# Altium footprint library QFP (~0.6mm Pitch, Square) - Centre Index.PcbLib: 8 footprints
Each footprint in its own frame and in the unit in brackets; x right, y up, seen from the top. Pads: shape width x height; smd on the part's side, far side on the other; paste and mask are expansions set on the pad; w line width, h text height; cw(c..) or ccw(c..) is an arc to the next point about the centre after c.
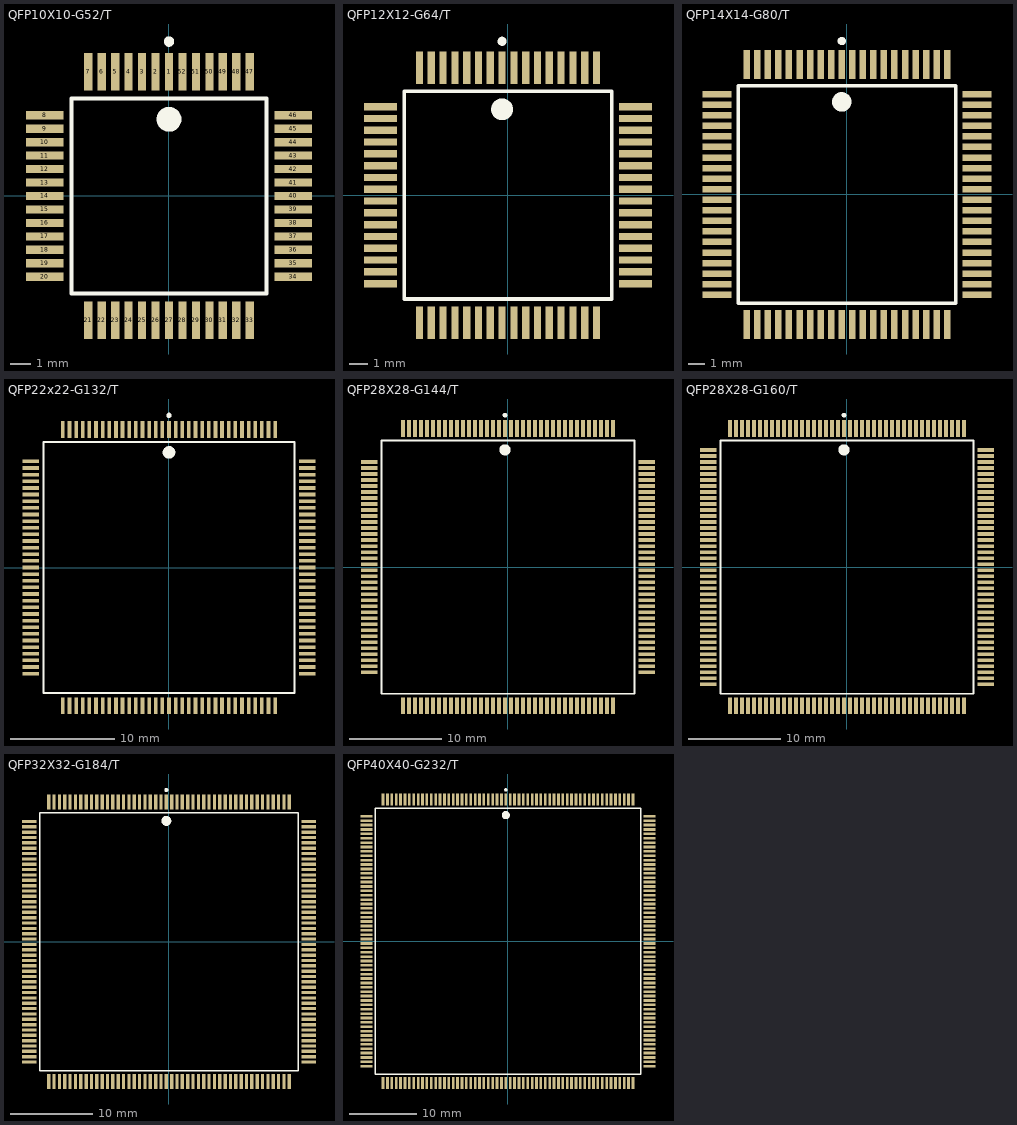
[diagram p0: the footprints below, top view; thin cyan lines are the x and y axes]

## QFP10X10-G52/T [mm]
pads (52):
  rect 0.4x1.8 smd: 1(0,6) 2(-0.65,6) 3(-1.3,6) 4(-1.95,6) 5(-2.6,6) 6(-3.25,6) 7(-3.9,6) 21(-3.9,-6) 22(-3.25,-6) 23(-2.6,-6) 24(-1.95,-6) 25(-1.3,-6) 26(-0.65,-6) 27(0,-6) 28(0.65,-6) 29(1.3,-6) 30(1.95,-6) 31(2.6,-6) 32(3.25,-6) 33(3.9,-6) 47(3.9,6) 48(3.25,6) 49(2.6,6) 50(1.95,6) 51(1.3,6) 52(0.65,6)
  rect 1.8x0.4 smd: 8(-6,3.9) 9(-6,3.25) 10(-6,2.6) 11(-6,1.95) 12(-6,1.3) 13(-6,0.65) 14(-6,0) 15(-6,-0.65) 16(-6,-1.3) 17(-6,-1.95) 18(-6,-2.6) 19(-6,-3.25) 20(-6,-3.9) 34(6,-3.9) 35(6,-3.25) 36(6,-2.6) 37(6,-1.95) 38(6,-1.3) 39(6,-0.65) 40(6,0) 41(6,0.65) 42(6,1.3) 43(6,1.95) 44(6,2.6) 45(6,3.25) 46(6,3.9)
Top Overlay:
  circle w0.6: c0,3.7 r0.3
  circle w0.25: c0,7.45 r0.125
  lines w0.2: -4.7,-4.7 -4.7,4.7 4.7,4.7 4.7,-4.7 -4.7,-4.7

## QFP12X12-G64/T [mm]
pads (64):
  rect 0.4x1.8 smd: 1(-0.325,7.025) 2(-0.975,7.025) 3(-1.625,7.025) 4(-2.275,7.025) 5(-2.925,7.025) 6(-3.575,7.025) 7(-4.225,7.025) 8(-4.875,7.025) 25(-4.875,-7.025) 26(-4.225,-7.025) 27(-3.575,-7.025) 28(-2.925,-7.025) 29(-2.275,-7.025) 30(-1.625,-7.025) 31(-0.975,-7.025) 32(-0.325,-7.025) 33(0.325,-7.025) 34(0.975,-7.025) 35(1.625,-7.025) 36(2.275,-7.025) 37(2.925,-7.025) 38(3.575,-7.025) 39(4.225,-7.025) 40(4.875,-7.025) 57(4.875,7.025) 58(4.225,7.025) 59(3.575,7.025) 60(2.925,7.025) 61(2.275,7.025) 62(1.625,7.025) 63(0.975,7.025) 64(0.325,7.025)
  rect 1.8x0.4 smd: 9(-7.025,4.875) 10(-7.025,4.225) 11(-7.025,3.575) 12(-7.025,2.925) 13(-7.025,2.275) 14(-7.025,1.625) 15(-7.025,0.975) 16(-7.025,0.325) 17(-7.025,-0.325) 18(-7.025,-0.975) 19(-7.025,-1.625) 20(-7.025,-2.275) 21(-7.025,-2.925) 22(-7.025,-3.575) 23(-7.025,-4.225) 24(-7.025,-4.875) 41(7.025,-4.875) 42(7.025,-4.225) 43(7.025,-3.575) 44(7.025,-2.925) 45(7.025,-2.275) 46(7.025,-1.625) 47(7.025,-0.975) 48(7.025,-0.325) 49(7.025,0.325) 50(7.025,0.975) 51(7.025,1.625) 52(7.025,2.275) 53(7.025,2.925) 54(7.025,3.575) 55(7.025,4.225) 56(7.025,4.875)
Top Overlay:
  circle w0.25: c-0.325,8.475 r0.125
  circle w0.6: c-0.325,4.725 r0.3
  lines w0.2: -5.725,-5.725 5.725,-5.725 5.725,5.725 -5.725,5.725 -5.725,-5.725

## QFP14X14-G80/T [mm]
pads (80):
  rect 0.4x1.8 smd: 1(-0.325,8) 2(-0.975,8) 3(-1.625,8) 4(-2.275,8) 5(-2.925,8) 6(-3.575,8) 7(-4.225,8) 8(-4.875,8) 9(-5.525,8) 10(-6.175,8) 31(-6.175,-8) 32(-5.525,-8) 33(-4.875,-8) 34(-4.225,-8) 35(-3.575,-8) 36(-2.925,-8) 37(-2.275,-8) 38(-1.625,-8) 39(-0.975,-8) 40(-0.325,-8) 41(0.325,-8) 42(0.975,-8) 43(1.625,-8) 44(2.275,-8) 45(2.925,-8) 46(3.575,-8) 47(4.225,-8) 48(4.875,-8) 49(5.525,-8) 50(6.175,-8) 71(6.175,8) 72(5.525,8) 73(4.875,8) 74(4.225,8) 75(3.575,8) 76(2.925,8) 77(2.275,8) 78(1.625,8) 79(0.975,8) 80(0.325,8)
  rect 1.8x0.4 smd: 11(-8,6.175) 12(-8,5.525) 13(-8,4.875) 14(-8,4.225) 15(-8,3.575) 16(-8,2.925) 17(-8,2.275) 18(-8,1.625) 19(-8,0.975) 20(-8,0.325) 21(-8,-0.325) 22(-8,-0.975) 23(-8,-1.625) 24(-8,-2.275) 25(-8,-2.925) 26(-8,-3.575) 27(-8,-4.225) 28(-8,-4.875) 29(-8,-5.525) 30(-8,-6.175) 51(8,-6.175) 52(8,-5.525) 53(8,-4.875) 54(8,-4.225) 55(8,-3.575) 56(8,-2.925) 57(8,-2.275) 58(8,-1.625) 59(8,-0.975) 60(8,-0.325) 61(8,0.325) 62(8,0.975) 63(8,1.625) 64(8,2.275) 65(8,2.925) 66(8,3.575) 67(8,4.225) 68(8,4.875) 69(8,5.525) 70(8,6.175)
Top Overlay:
  circle w0.25: c-0.325,9.45 r0.125
  circle w0.6: c-0.325,5.7 r0.3
  lines w0.2: -6.7,-6.7 6.7,-6.7 6.7,6.7 -6.7,6.7 -6.7,-6.7

## QFP22x22-G132/T [mm]
pads (132):
  rect 0.35x1.6 smd: 1(0,13.225) 2(-0.635,13.225) 3(-1.27,13.225) 4(-1.905,13.225) 5(-2.54,13.225) 6(-3.175,13.225) 7(-3.81,13.225) 8(-4.445,13.225) 9(-5.08,13.225) 10(-5.715,13.225) 11(-6.35,13.225) 12(-6.985,13.225) 13(-7.62,13.225) 14(-8.255,13.225) 15(-8.89,13.225) 16(-9.525,13.225) 17(-10.16,13.225) 51(-10.16,-13.225) 52(-9.525,-13.225) 53(-8.89,-13.225) 54(-8.255,-13.225) 55(-7.62,-13.225) 56(-6.985,-13.225) 57(-6.35,-13.225) 58(-5.715,-13.225) 59(-5.08,-13.225) 60(-4.445,-13.225) 61(-3.81,-13.225) 62(-3.175,-13.225) 63(-2.54,-13.225) 64(-1.905,-13.225) 65(-1.27,-13.225) 66(-0.635,-13.225) 67(0,-13.225) 68(0.635,-13.225) 69(1.27,-13.225) 70(1.905,-13.225) 71(2.54,-13.225) 72(3.175,-13.225) 73(3.81,-13.225) 74(4.445,-13.225) 75(5.08,-13.225) 76(5.715,-13.225) 77(6.35,-13.225) 78(6.985,-13.225) 79(7.62,-13.225) 80(8.255,-13.225) 81(8.89,-13.225) 82(9.525,-13.225) 83(10.16,-13.225) 117(10.16,13.225) 118(9.525,13.225) 119(8.89,13.225) 120(8.255,13.225) 121(7.62,13.225) 122(6.985,13.225) 123(6.35,13.225) 124(5.715,13.225) 125(5.08,13.225) 126(4.445,13.225) 127(3.81,13.225) 128(3.175,13.225) 129(2.54,13.225) 130(1.905,13.225) 131(1.27,13.225) 132(0.635,13.225)
  rect 1.6x0.35 smd: 18(-13.225,10.16) 19(-13.225,9.525) 20(-13.225,8.89) 21(-13.225,8.255) 22(-13.225,7.62) 23(-13.225,6.985) 24(-13.225,6.35) 25(-13.225,5.715) 26(-13.225,5.08) 27(-13.225,4.445) 28(-13.225,3.81) 29(-13.225,3.175) 30(-13.225,2.54) 31(-13.225,1.905) 32(-13.225,1.27) 33(-13.225,0.635) 34(-13.225,0) 35(-13.225,-0.635) 36(-13.225,-1.27) 37(-13.225,-1.905) 38(-13.225,-2.54) 39(-13.225,-3.175) 40(-13.225,-3.81) 41(-13.225,-4.445) 42(-13.225,-5.08) 43(-13.225,-5.715) 44(-13.225,-6.35) 45(-13.225,-6.985) 46(-13.225,-7.62) 47(-13.225,-8.255) 48(-13.225,-8.89) 49(-13.225,-9.525) 50(-13.225,-10.16) 84(13.225,-10.16) 85(13.225,-9.525) 86(13.225,-8.89) 87(13.225,-8.255) 88(13.225,-7.62) 89(13.225,-6.985) 90(13.225,-6.35) 91(13.225,-5.715) 92(13.225,-5.08) 93(13.225,-4.445) 94(13.225,-3.81) 95(13.225,-3.175) 96(13.225,-2.54) 97(13.225,-1.905) 98(13.225,-1.27) 99(13.225,-0.635) 100(13.225,0) 101(13.225,0.635) 102(13.225,1.27) 103(13.225,1.905) 104(13.225,2.54) 105(13.225,3.175) 106(13.225,3.81) 107(13.225,4.445) 108(13.225,5.08) 109(13.225,5.715) 110(13.225,6.35) 111(13.225,6.985) 112(13.225,7.62) 113(13.225,8.255) 114(13.225,8.89) 115(13.225,9.525) 116(13.225,10.16)
Top Overlay:
  circle w0.25: c0,14.575 r0.125
  circle w0.6: c0,11.025 r0.3
  lines w0.2: -12.025,-12.025 12.025,-12.025 12.025,12.025 -12.025,12.025 -12.025,-12.025

## QFP28X28-G144/T [mm]
pads (144):
  rect 0.4x1.8 smd: 1(-0.325,15) 2(-0.975,15) 3(-1.625,15) 4(-2.275,15) 5(-2.925,15) 6(-3.575,15) 7(-4.225,15) 8(-4.875,15) 9(-5.525,15) 10(-6.175,15) 11(-6.825,15) 12(-7.475,15) 13(-8.125,15) 14(-8.775,15) 15(-9.425,15) 16(-10.075,15) 17(-10.725,15) 18(-11.375,15) 55(-11.375,-15) 56(-10.725,-15) 57(-10.075,-15) 58(-9.425,-15) 59(-8.775,-15) 60(-8.125,-15) 61(-7.475,-15) 62(-6.825,-15) 63(-6.175,-15) 64(-5.525,-15) 65(-4.875,-15) 66(-4.225,-15) 67(-3.575,-15) 68(-2.925,-15) 69(-2.275,-15) 70(-1.625,-15) 71(-0.975,-15) 72(-0.325,-15) 73(0.325,-15) 74(0.975,-15) 75(1.625,-15) 76(2.275,-15) 77(2.925,-15) 78(3.575,-15) 79(4.225,-15) 80(4.875,-15) 81(5.525,-15) 82(6.175,-15) 83(6.825,-15) 84(7.475,-15) 85(8.125,-15) 86(8.775,-15) 87(9.425,-15) 88(10.075,-15) 89(10.725,-15) 90(11.375,-15) 127(11.375,15) 128(10.725,15) 129(10.075,15) 130(9.425,15) 131(8.775,15) 132(8.125,15) 133(7.475,15) 134(6.825,15) 135(6.175,15) 136(5.525,15) 137(4.875,15) 138(4.225,15) 139(3.575,15) 140(2.925,15) 141(2.275,15) 142(1.625,15) 143(0.975,15) 144(0.325,15)
  rect 1.8x0.4 smd: 19(-15,11.375) 20(-15,10.725) 21(-15,10.075) 22(-15,9.425) 23(-15,8.775) 24(-15,8.125) 25(-15,7.475) 26(-15,6.825) 27(-15,6.175) 28(-15,5.525) 29(-15,4.875) 30(-15,4.225) 31(-15,3.575) 32(-15,2.925) 33(-15,2.275) 34(-15,1.625) 35(-15,0.975) 36(-15,0.325) 37(-15,-0.325) 38(-15,-0.975) 39(-15,-1.625) 40(-15,-2.275) 41(-15,-2.925) 42(-15,-3.575) 43(-15,-4.225) 44(-15,-4.875) 45(-15,-5.525) 46(-15,-6.175) 47(-15,-6.825) 48(-15,-7.475) 49(-15,-8.125) 50(-15,-8.775) 51(-15,-9.425) 52(-15,-10.075) 53(-15,-10.725) 54(-15,-11.375) 91(15,-11.375) 92(15,-10.725) 93(15,-10.075) 94(15,-9.425) 95(15,-8.775) 96(15,-8.125) 97(15,-7.475) 98(15,-6.825) 99(15,-6.175) 100(15,-5.525) 101(15,-4.875) 102(15,-4.225) 103(15,-3.575) 104(15,-2.925) 105(15,-2.275) 106(15,-1.625) 107(15,-0.975) 108(15,-0.325) 109(15,0.325) 110(15,0.975) 111(15,1.625) 112(15,2.275) 113(15,2.925) 114(15,3.575) 115(15,4.225) 116(15,4.875) 117(15,5.525) 118(15,6.175) 119(15,6.825) 120(15,7.475) 121(15,8.125) 122(15,8.775) 123(15,9.425) 124(15,10.075) 125(15,10.725) 126(15,11.375)
Top Overlay:
  circle w0.6: c-0.325,12.7 r0.3
  circle w0.25: c-0.325,16.45 r0.125
  lines w0.2: -13.7,-13.7 -13.7,13.7 13.7,13.7 13.7,-13.7 -13.7,-13.7

## QFP28X28-G160/T [mm]
pads (160):
  rect 0.4x1.8 smd: 1(-0.325,15) 2(-0.975,15) 3(-1.625,15) 4(-2.275,15) 5(-2.925,15) 6(-3.575,15) 7(-4.225,15) 8(-4.875,15) 9(-5.525,15) 10(-6.175,15) 11(-6.825,15) 12(-7.475,15) 13(-8.125,15) 14(-8.775,15) 15(-9.425,15) 16(-10.075,15) 17(-10.725,15) 18(-11.375,15) 19(-12.025,15) 20(-12.675,15) 61(-12.675,-15) 62(-12.025,-15) 63(-11.375,-15) 64(-10.725,-15) 65(-10.075,-15) 66(-9.425,-15) 67(-8.775,-15) 68(-8.125,-15) 69(-7.475,-15) 70(-6.825,-15) 71(-6.175,-15) 72(-5.525,-15) 73(-4.875,-15) 74(-4.225,-15) 75(-3.575,-15) 76(-2.925,-15) 77(-2.275,-15) 78(-1.625,-15) 79(-0.975,-15) 80(-0.325,-15) 81(0.325,-15) 82(0.975,-15) 83(1.625,-15) 84(2.275,-15) 85(2.925,-15) 86(3.575,-15) 87(4.225,-15) 88(4.875,-15) 89(5.525,-15) 90(6.175,-15) 91(6.825,-15) 92(7.475,-15) 93(8.125,-15) 94(8.775,-15) 95(9.425,-15) 96(10.075,-15) 97(10.725,-15) 98(11.375,-15) 99(12.025,-15) 100(12.675,-15) 141(12.675,15) 142(12.025,15) 143(11.375,15) 144(10.725,15) 145(10.075,15) 146(9.425,15) 147(8.775,15) 148(8.125,15) 149(7.475,15) 150(6.825,15) 151(6.175,15) 152(5.525,15) 153(4.875,15) 154(4.225,15) 155(3.575,15) 156(2.925,15) 157(2.275,15) 158(1.625,15) 159(0.975,15) 160(0.325,15)
  rect 1.8x0.4 smd: 21(-15,12.675) 22(-15,12.025) 23(-15,11.375) 24(-15,10.725) 25(-15,10.075) 26(-15,9.425) 27(-15,8.775) 28(-15,8.125) 29(-15,7.475) 30(-15,6.825) 31(-15,6.175) 32(-15,5.525) 33(-15,4.875) 34(-15,4.225) 35(-15,3.575) 36(-15,2.925) 37(-15,2.275) 38(-15,1.625) 39(-15,0.975) 40(-15,0.325) 41(-15,-0.325) 42(-15,-0.975) 43(-15,-1.625) 44(-15,-2.275) 45(-15,-2.925) 46(-15,-3.575) 47(-15,-4.225) 48(-15,-4.875) 49(-15,-5.525) 50(-15,-6.175) 51(-15,-6.825) 52(-15,-7.475) 53(-15,-8.125) 54(-15,-8.775) 55(-15,-9.425) 56(-15,-10.075) 57(-15,-10.725) 58(-15,-11.375) 59(-15,-12.025) 60(-15,-12.675) 101(15,-12.675) 102(15,-12.025) 103(15,-11.375) 104(15,-10.725) 105(15,-10.075) 106(15,-9.425) 107(15,-8.775) 108(15,-8.125) 109(15,-7.475) 110(15,-6.825) 111(15,-6.175) 112(15,-5.525) 113(15,-4.875) 114(15,-4.225) 115(15,-3.575) 116(15,-2.925) 117(15,-2.275) 118(15,-1.625) 119(15,-0.975) 120(15,-0.325) 121(15,0.325) 122(15,0.975) 123(15,1.625) 124(15,2.275) 125(15,2.925) 126(15,3.575) 127(15,4.225) 128(15,4.875) 129(15,5.525) 130(15,6.175) 131(15,6.825) 132(15,7.475) 133(15,8.125) 134(15,8.775) 135(15,9.425) 136(15,10.075) 137(15,10.725) 138(15,11.375) 139(15,12.025) 140(15,12.675)
Top Overlay:
  circle w0.25: c-0.325,16.45 r0.125
  circle w0.6: c-0.325,12.7 r0.3
  lines w0.2: -13.7,-13.7 13.7,-13.7 13.7,13.7 -13.7,13.7 -13.7,-13.7

## QFP32X32-G184/T [mm]
pads (184):
  rect 0.4x1.8 smd: 1(-0.325,17) 2(-0.975,17) 3(-1.625,17) 4(-2.275,17) 5(-2.925,17) 6(-3.575,17) 7(-4.225,17) 8(-4.875,17) 9(-5.525,17) 10(-6.175,17) 11(-6.825,17) 12(-7.475,17) 13(-8.125,17) 14(-8.775,17) 15(-9.425,17) 16(-10.075,17) 17(-10.725,17) 18(-11.375,17) 19(-12.025,17) 20(-12.675,17) 21(-13.325,17) 22(-13.975,17) 23(-14.625,17) 70(-14.625,-17) 71(-13.975,-17) 72(-13.325,-17) 73(-12.675,-17) 74(-12.025,-17) 75(-11.375,-17) 76(-10.725,-17) 77(-10.075,-17) 78(-9.425,-17) 79(-8.775,-17) 80(-8.125,-17) 81(-7.475,-17) 82(-6.825,-17) 83(-6.175,-17) 84(-5.525,-17) 85(-4.875,-17) 86(-4.225,-17) 87(-3.575,-17) 88(-2.925,-17) 89(-2.275,-17) 90(-1.625,-17) 91(-0.975,-17) 92(-0.325,-17) 93(0.325,-17) 94(0.975,-17) 95(1.625,-17) 96(2.275,-17) 97(2.925,-17) 98(3.575,-17) 99(4.225,-17) 100(4.875,-17) 101(5.525,-17) 102(6.175,-17) 103(6.825,-17) 104(7.475,-17) 105(8.125,-17) 106(8.775,-17) 107(9.425,-17) 108(10.075,-17) 109(10.725,-17) 110(11.375,-17) 111(12.025,-17) 112(12.675,-17) 113(13.325,-17) 114(13.975,-17) 115(14.625,-17) 162(14.625,17) 163(13.975,17) 164(13.325,17) 165(12.675,17) 166(12.025,17) 167(11.375,17) 168(10.725,17) 169(10.075,17) 170(9.425,17) 171(8.775,17) 172(8.125,17) 173(7.475,17) 174(6.825,17) 175(6.175,17) 176(5.525,17) 177(4.875,17) 178(4.225,17) 179(3.575,17) 180(2.925,17) 181(2.275,17) 182(1.625,17) 183(0.975,17) 184(0.325,17)
  rect 1.8x0.4 smd: 24(-17,14.625) 25(-17,13.975) 26(-17,13.325) 27(-17,12.675) 28(-17,12.025) 29(-17,11.375) 30(-17,10.725) 31(-17,10.075) 32(-17,9.425) 33(-17,8.775) 34(-17,8.125) 35(-17,7.475) 36(-17,6.825) 37(-17,6.175) 38(-17,5.525) 39(-17,4.875) 40(-17,4.225) 41(-17,3.575) 42(-17,2.925) 43(-17,2.275) 44(-17,1.625) 45(-17,0.975) 46(-17,0.325) 47(-17,-0.325) 48(-17,-0.975) 49(-17,-1.625) 50(-17,-2.275) 51(-17,-2.925) 52(-17,-3.575) 53(-17,-4.225) 54(-17,-4.875) 55(-17,-5.525) 56(-17,-6.175) 57(-17,-6.825) 58(-17,-7.475) 59(-17,-8.125) 60(-17,-8.775) 61(-17,-9.425) 62(-17,-10.075) 63(-17,-10.725) 64(-17,-11.375) 65(-17,-12.025) 66(-17,-12.675) 67(-17,-13.325) 68(-17,-13.975) 69(-17,-14.625) 116(17,-14.625) 117(17,-13.975) 118(17,-13.325) 119(17,-12.675) 120(17,-12.025) 121(17,-11.375) 122(17,-10.725) 123(17,-10.075) 124(17,-9.425) 125(17,-8.775) 126(17,-8.125) 127(17,-7.475) 128(17,-6.825) 129(17,-6.175) 130(17,-5.525) 131(17,-4.875) 132(17,-4.225) 133(17,-3.575) 134(17,-2.925) 135(17,-2.275) 136(17,-1.625) 137(17,-0.975) 138(17,-0.325) 139(17,0.325) 140(17,0.975) 141(17,1.625) 142(17,2.275) 143(17,2.925) 144(17,3.575) 145(17,4.225) 146(17,4.875) 147(17,5.525) 148(17,6.175) 149(17,6.825) 150(17,7.475) 151(17,8.125) 152(17,8.775) 153(17,9.425) 154(17,10.075) 155(17,10.725) 156(17,11.375) 157(17,12.025) 158(17,12.675) 159(17,13.325) 160(17,13.975) 161(17,14.625)
Top Overlay:
  circle w0.25: c-0.325,18.45 r0.125
  circle w0.6: c-0.325,14.7 r0.3
  lines w0.2: -15.7,-15.7 15.7,-15.7 15.7,15.7 -15.7,15.7 -15.7,-15.7

## QFP40X40-G232/T [mm]
pads (232):
  rect 0.4x1.8 smd: 1(-0.325,21) 2(-0.975,21) 3(-1.625,21) 4(-2.275,21) 5(-2.925,21) 6(-3.575,21) 7(-4.225,21) 8(-4.875,21) 9(-5.525,21) 10(-6.175,21) 11(-6.825,21) 12(-7.475,21) 13(-8.125,21) 14(-8.775,21) 15(-9.425,21) 16(-10.075,21) 17(-10.725,21) 18(-11.375,21) 19(-12.025,21) 20(-12.675,21) 21(-13.325,21) 22(-13.975,21) 23(-14.625,21) 24(-15.275,21) 25(-15.925,21) 26(-16.575,21) 27(-17.225,21) 28(-17.875,21) 29(-18.525,21) 88(-18.525,-21) 89(-17.875,-21) 90(-17.225,-21) 91(-16.575,-21) 92(-15.925,-21) 93(-15.275,-21) 94(-14.625,-21) 95(-13.975,-21) 96(-13.325,-21) 97(-12.675,-21) 98(-12.025,-21) 99(-11.375,-21) 100(-10.725,-21) 101(-10.075,-21) 102(-9.425,-21) 103(-8.775,-21) 104(-8.125,-21) 105(-7.475,-21) 106(-6.825,-21) 107(-6.175,-21) 108(-5.525,-21) 109(-4.875,-21) 110(-4.225,-21) 111(-3.575,-21) 112(-2.925,-21) 113(-2.275,-21) 114(-1.625,-21) 115(-0.975,-21) 116(-0.325,-21) 117(0.325,-21) 118(0.975,-21) 119(1.625,-21) 120(2.275,-21) 121(2.925,-21) 122(3.575,-21) 123(4.225,-21) 124(4.875,-21) 125(5.525,-21) 126(6.175,-21) 127(6.825,-21) 128(7.475,-21) 129(8.125,-21) 130(8.775,-21) 131(9.425,-21) 132(10.075,-21) 133(10.725,-21) 134(11.375,-21) 135(12.025,-21) 136(12.675,-21) 137(13.325,-21) 138(13.975,-21) 139(14.625,-21) 140(15.275,-21) 141(15.925,-21) 142(16.575,-21) 143(17.225,-21) 144(17.875,-21) 145(18.525,-21) 204(18.525,21) 205(17.875,21) 206(17.225,21) 207(16.575,21) 208(15.925,21) 209(15.275,21) 210(14.625,21) 211(13.975,21) 212(13.325,21) 213(12.675,21) 214(12.025,21) 215(11.375,21) 216(10.725,21) 217(10.075,21) 218(9.425,21) 219(8.775,21) 220(8.125,21) 221(7.475,21) 222(6.825,21) 223(6.175,21) 224(5.525,21) 225(4.875,21) 226(4.225,21) 227(3.575,21) 228(2.925,21) 229(2.275,21) 230(1.625,21) 231(0.975,21) 232(0.325,21)
  rect 1.8x0.4 smd: 30(-21,18.525) 31(-21,17.875) 32(-21,17.225) 33(-21,16.575) 34(-21,15.925) 35(-21,15.275) 36(-21,14.625) 37(-21,13.975) 38(-21,13.325) 39(-21,12.675) 40(-21,12.025) 41(-21,11.375) 42(-21,10.725) 43(-21,10.075) 44(-21,9.425) 45(-21,8.775) 46(-21,8.125) 47(-21,7.475) 48(-21,6.825) 49(-21,6.175) 50(-21,5.525) 51(-21,4.875) 52(-21,4.225) 53(-21,3.575) 54(-21,2.925) 55(-21,2.275) 56(-21,1.625) 57(-21,0.975) 58(-21,0.325) 59(-21,-0.325) 60(-21,-0.975) 61(-21,-1.625) 62(-21,-2.275) 63(-21,-2.925) 64(-21,-3.575) 65(-21,-4.225) 66(-21,-4.875) 67(-21,-5.525) 68(-21,-6.175) 69(-21,-6.825) 70(-21,-7.475) 71(-21,-8.125) 72(-21,-8.775) 73(-21,-9.425) 74(-21,-10.075) 75(-21,-10.725) 76(-21,-11.375) 77(-21,-12.025) 78(-21,-12.675) 79(-21,-13.325) 80(-21,-13.975) 81(-21,-14.625) 82(-21,-15.275) 83(-21,-15.925) 84(-21,-16.575) 85(-21,-17.225) 86(-21,-17.875) 87(-21,-18.525) 146(21,-18.525) 147(21,-17.875) 148(21,-17.225) 149(21,-16.575) 150(21,-15.925) 151(21,-15.275) 152(21,-14.625) 153(21,-13.975) 154(21,-13.325) 155(21,-12.675) 156(21,-12.025) 157(21,-11.375) 158(21,-10.725) 159(21,-10.075) 160(21,-9.425) 161(21,-8.775) 162(21,-8.125) 163(21,-7.475) 164(21,-6.825) 165(21,-6.175) 166(21,-5.525) 167(21,-4.875) 168(21,-4.225) 169(21,-3.575) 170(21,-2.925) 171(21,-2.275) 172(21,-1.625) 173(21,-0.975) 174(21,-0.325) 175(21,0.325) 176(21,0.975) 177(21,1.625) 178(21,2.275) 179(21,2.925) 180(21,3.575) 181(21,4.225) 182(21,4.875) 183(21,5.525) 184(21,6.175) 185(21,6.825) 186(21,7.475) 187(21,8.125) 188(21,8.775) 189(21,9.425) 190(21,10.075) 191(21,10.725) 192(21,11.375) 193(21,12.025) 194(21,12.675) 195(21,13.325) 196(21,13.975) 197(21,14.625) 198(21,15.275) 199(21,15.925) 200(21,16.575) 201(21,17.225) 202(21,17.875) 203(21,18.525)
Top Overlay:
  circle w0.6: c-0.325,18.7 r0.3
  circle w0.25: c-0.325,22.45 r0.125
  lines w0.2: -19.7,-19.7 -19.7,19.7 19.7,19.7 19.7,-19.7 -19.7,-19.7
